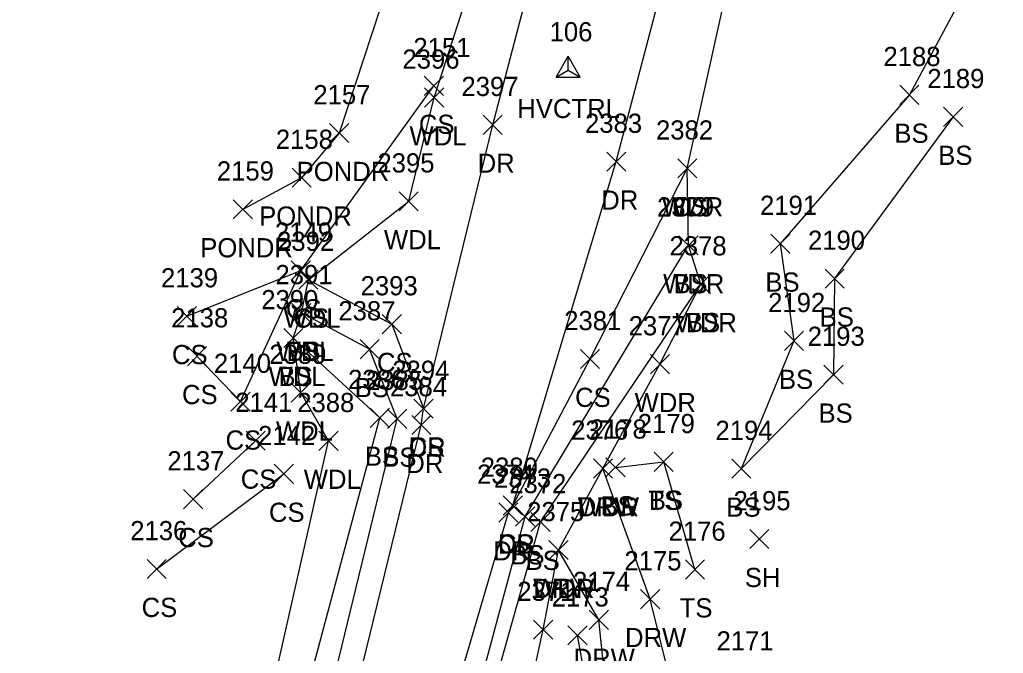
# Model space of a CAD drawing. Extents: x 1761340 to 1763889, y 696770 to 706023.
# Drawn here: x 1761653.6 to 1761756.2, y 700983.6 to 701049.7 of the extents above; entities that cross this region are included whole.
import ezdxf

# ---------------------------------------------------------------- set-up
doc = ezdxf.new("R2010")
doc.units = 0
for name, color, linetype in [('C_A', 7, 'Continuous'), ('C_I', 7, 'Continuous'), ('CPSM', 7, 'Continuous'), ('L_A', 7, 'Continuous'), ('L_I', 7, 'Continuous'), ('L_TIC', 7, 'Continuous'), ('LAWA', 7, 'Continuous'), ('LAWE', 7, 'Continuous'), ('LELB', 7, 'Continuous'), ('R_A', 7, 'Continuous'), ('R_I', 7, 'Continuous'), ('R_TIC', 7, 'Continuous'), ('RDP', 7, 'Continuous'), ('RDW', 7, 'Continuous')]:
    doc.layers.add(name, color=color, linetype=linetype)

msp = doc.modelspace()

# ---------------------------------------------------------------- linework, layer by layer
at = {"layer": 'CPSM'}
for p, q in [((1761709.57, 701043.69), (1761710.82, 701045.86)), ((1761712.07, 701043.69), (1761710.82, 701045.86)), ((1761710.82, 701044.42), (1761710.82, 701045.86)), ((1761709.57, 701043.69), (1761710.82, 701044.42)), ((1761710.82, 701044.42), (1761710.82, 701044.42)), ((1761710.82, 701044.42), (1761712.07, 701043.69)), ((1761709.57, 701043.69), (1761712.07, 701043.69))]:
    msp.add_line(p, q, dxfattribs=at)
at = {"layer": 'L_TIC'}
for points in [[(1761695.82, 701041.77), (1761697.82, 701043.77)], [(1761697.82, 701041.77), (1761695.82, 701043.77)], [(1761695.86, 701040.57), (1761697.86, 701042.57)], [(1761697.86, 701040.57), (1761695.86, 701042.57)], [(1761745.39, 701040.84), (1761747.39, 701042.84)], [(1761747.39, 701040.84), (1761745.39, 701042.84)], [(1761749.96, 701038.54), (1761751.96, 701040.54)], [(1761751.96, 701038.54), (1761749.96, 701040.54)], [(1761685.95, 701036.86), (1761687.95, 701038.86)], [(1761687.95, 701036.86), (1761685.95, 701038.86)], [(1761722.24, 701033.18), (1761724.24, 701035.18)], [(1761724.24, 701033.18), (1761722.24, 701035.18)], [(1761722.24, 701033.18), (1761724.24, 701035.18)], [(1761724.24, 701033.18), (1761722.24, 701035.18)], [(1761682.04, 701032.21), (1761684.04, 701034.21)], [(1761684.04, 701032.21), (1761682.04, 701034.21)], [(1761693.2, 701029.75), (1761695.2, 701031.75)], [(1761695.2, 701029.75), (1761693.2, 701031.75)], [(1761675.9, 701028.91), (1761677.9, 701030.91)], [(1761677.9, 701028.91), (1761675.9, 701030.91)], [(1761722.36, 701025.16), (1761724.36, 701027.16)], [(1761724.36, 701025.16), (1761722.36, 701027.16)], [(1761722.36, 701025.16), (1761724.36, 701027.16)], [(1761724.36, 701025.16), (1761722.36, 701027.16)], [(1761731.94, 701025.33), (1761733.94, 701027.33)], [(1761733.94, 701025.33), (1761731.94, 701027.33)], [(1761681.96, 701022.54), (1761683.96, 701024.54)], [(1761683.96, 701022.54), (1761681.96, 701024.54)], [(1761681.96, 701022.54), (1761683.96, 701024.54)], [(1761683.96, 701022.54), (1761681.96, 701024.54)], [(1761682.74, 701021.58), (1761684.74, 701023.58)], [(1761684.74, 701021.58), (1761682.74, 701023.58)], [(1761682.74, 701021.58), (1761684.74, 701023.58)], [(1761684.74, 701021.58), (1761682.74, 701023.58)], [(1761723.65, 701021.11), (1761725.65, 701023.11)], [(1761725.65, 701021.11), (1761723.65, 701023.11)], [(1761723.65, 701021.11), (1761725.65, 701023.11)], [(1761725.65, 701021.11), (1761723.65, 701023.11)], [(1761737.6, 701021.69), (1761739.6, 701023.69)], [(1761739.6, 701021.69), (1761737.6, 701023.69)], [(1761670.08, 701017.78), (1761672.08, 701019.78)], [(1761672.08, 701017.78), (1761670.08, 701019.78)], [(1761682.01, 701018.11), (1761684.01, 701020.11)], [(1761684.01, 701018.11), (1761682.01, 701020.11)], [(1761682.01, 701018.11), (1761684.01, 701020.11)], [(1761684.01, 701018.11), (1761682.01, 701020.11)], [(1761691.44, 701016.95), (1761693.44, 701018.95)], [(1761693.44, 701016.95), (1761691.44, 701018.95)], [(1761681.17, 701015.5), (1761683.17, 701017.5)], [(1761683.17, 701015.5), (1761681.17, 701017.5)], [(1761681.17, 701015.5), (1761683.17, 701017.5)], [(1761683.17, 701015.5), (1761681.17, 701017.5)], [(1761733.36, 701015.2), (1761735.36, 701017.2)], [(1761735.36, 701015.2), (1761733.36, 701017.2)], [(1761689.13, 701014.34), (1761691.13, 701016.34)], [(1761691.13, 701014.34), (1761689.13, 701016.34)], [(1761671.13, 701013.61), (1761673.13, 701015.61)], [(1761673.13, 701013.61), (1761671.13, 701015.61)], [(1761712.1, 701013.32), (1761714.1, 701015.32)], [(1761714.1, 701013.32), (1761712.1, 701015.32)], [(1761719.39, 701012.78), (1761721.39, 701014.78)], [(1761721.39, 701012.78), (1761719.39, 701014.78)], [(1761737.48, 701011.68), (1761739.48, 701013.68)], [(1761739.48, 701011.68), (1761737.48, 701013.68)], [(1761681.94, 701009.81), (1761683.94, 701011.81)], [(1761683.94, 701009.81), (1761681.94, 701011.81)], [(1761675.67, 701008.87), (1761677.67, 701010.87)], [(1761677.67, 701008.87), (1761675.67, 701010.87)], [(1761694.75, 701008.14), (1761696.75, 701010.14)], [(1761696.75, 701008.14), (1761694.75, 701010.14)], [(1761690.19, 701007.19), (1761692.19, 701009.19)], [(1761692.19, 701007.19), (1761690.19, 701009.19)], [(1761692, 701007.08), (1761694, 701009.08)], [(1761694, 701007.08), (1761692, 701009.08)], [(1761677.24, 701004.8), (1761679.24, 701006.8)], [(1761679.24, 701004.8), (1761677.24, 701006.8)], [(1761684.84, 701004.78), (1761686.84, 701006.78)], [(1761686.84, 701004.78), (1761684.84, 701006.78)], [(1761719.78, 701002.59), (1761721.78, 701004.59)], [(1761721.78, 701002.59), (1761719.78, 701004.59)], [(1761719.78, 701002.59), (1761721.78, 701004.59)], [(1761721.78, 701002.59), (1761719.78, 701004.59)], [(1761713.45, 701001.91), (1761715.45, 701003.91)], [(1761715.45, 701001.91), (1761713.45, 701003.91)], [(1761714.76, 701002.02), (1761716.76, 701004.02)], [(1761716.76, 701002.02), (1761714.76, 701004.02)], [(1761727.87, 701001.88), (1761729.87, 701003.88)], [(1761729.87, 701001.88), (1761727.87, 701003.88)], [(1761727.87, 701001.88), (1761729.87, 701003.88)], [(1761729.87, 701001.88), (1761727.87, 701003.88)], [(1761680.19, 701001.34), (1761682.19, 701003.34)], [(1761682.19, 701001.34), (1761680.19, 701003.34)], [(1761670.73, 700998.71), (1761672.73, 701000.71)], [(1761672.73, 700998.71), (1761670.73, 701000.71)], [(1761704.06, 700998.04), (1761706.06, 701000.04)], [(1761706.06, 700998.04), (1761704.06, 701000.04)], [(1761705.35, 700996.91), (1761707.35, 700998.91)], [(1761707.35, 700996.91), (1761705.35, 700998.91)], [(1761706.94, 700996.33), (1761708.94, 700998.33)], [(1761708.94, 700996.33), (1761706.94, 700998.33)], [(1761729.75, 700994.55), (1761731.75, 700996.55)], [(1761731.75, 700994.55), (1761729.75, 700996.55)], [(1761708.81, 700993.41), (1761710.81, 700995.41)], [(1761710.81, 700993.41), (1761708.81, 700995.41)], [(1761666.92, 700991.43), (1761668.92, 700993.43)], [(1761668.92, 700991.43), (1761666.92, 700993.43)], [(1761723.04, 700991.38), (1761725.04, 700993.38)], [(1761725.04, 700991.38), (1761723.04, 700993.38)], [(1761707.21, 700985.11), (1761709.21, 700987.11)], [(1761709.21, 700985.11), (1761707.21, 700987.11)], [(1761710.79, 700984.52), (1761712.79, 700986.52)], [(1761712.79, 700984.52), (1761710.79, 700986.52)]]:
    msp.add_lwpolyline(points, dxfattribs=at)
at = {"layer": 'LAWA'}
for points in [[(1761667.45, 700938.83), (1761676.85, 700965.95), (1761685.84, 701005.78), (1761682.94, 701010.81), (1761682.17, 701016.5), (1761683.01, 701019.11), (1761683.74, 701022.58), (1761694.2, 701030.75), (1761696.86, 701041.57), (1761703.63, 701062.52), (1761706.63, 701075.37), (1761702.24, 701098.48), (1761699.3, 701099.16), (1761706.74, 701121.1), (1761714.05, 701139.55)], [(1761683.19, 700893.77), (1761693.76, 700930.8), (1761702.56, 700960.09), (1761708.21, 700986.11), (1761709.81, 700994.41), (1761714.45, 701002.91), (1761720.39, 701013.78), (1761724.65, 701022.11), (1761723.36, 701026.16), (1761723.24, 701034.18), (1761732.59, 701076.41), (1761747, 701128.03)]]:
    msp.add_lwpolyline(points, dxfattribs=at)
at = {"layer": 'LAWE'}
msp.add_lwpolyline([(1761695.98, 701076.99), (1761695.44, 701063.67), (1761686.95, 701037.86), (1761683.04, 701033.21), (1761676.9, 701029.91)], dxfattribs=at)
at = {"layer": 'LELB'}
for points in [[(1761765.71, 701062.95), (1761753.76, 701055.58), (1761746.39, 701041.84), (1761732.94, 701026.33), (1761734.36, 701016.2), (1761728.87, 701002.88)], [(1761672.13, 701014.61), (1761676.67, 701009.87), (1761682.96, 701023.54), (1761696.82, 701042.77)], [(1761750.96, 701039.54), (1761738.6, 701022.69), (1761738.48, 701012.68), (1761728.87, 701002.88)], [(1761705.06, 700999.04), (1761713.1, 701014.32), (1761723.24, 701034.18)], [(1761681.3, 700585.52), (1761671.93, 700613.51), (1761667.59, 700648.27), (1761662.96, 700684.4), (1761660.97, 700720.86), (1761660.49, 700762.08), (1761662.81, 700791.59), (1761666.16, 700822.15), (1761669.09, 700835.75), (1761669.55, 700847.22), (1761671.38, 700859.7), (1761679.65, 700896.38), (1761688.23, 700933.04), (1761696.4, 700960.96), (1761706.35, 700997.91), (1761723.36, 701026.16)], [(1761671.08, 701018.78), (1761682.96, 701023.54)], [(1761684.45, 700586.47), (1761674.15, 700613.84), (1761669.56, 700648.24), (1761665.94, 700684.58), (1761663.69, 700720.73), (1761662.67, 700762.27), (1761665.11, 700791.25), (1761666.95, 700822.18), (1761669.97, 700835.61), (1761670.38, 700847.09), (1761671.95, 700859.51), (1761680.67, 700895.81), (1761689.74, 700932.61), (1761697.72, 700961.08), (1761707.94, 700997.33), (1761724.65, 701022.11)], [(1761683.74, 701022.58), (1761692.44, 701017.95), (1761695.75, 701009.14)], [(1761650.67, 700568.58), (1761653.72, 700589.35), (1761656.23, 700611.85), (1761650.78, 700645.88), (1761646.69, 700682.27), (1761643.97, 700721.14), (1761646.18, 700763.15), (1761649, 700791.97), (1761651.08, 700826.68), (1761655.56, 700862.86), (1761665.44, 700900.35), (1761673.53, 700937.72), (1761682.38, 700964.35), (1761693, 701008.08), (1761690.13, 701015.34), (1761683.01, 701019.11)], [(1761647.36, 700568.69), (1761651.51, 700589.64), (1761652.18, 700611.17), (1761648.15, 700645.92), (1761644.28, 700683.03), (1761641.56, 700721.37), (1761643.75, 700763.66), (1761644.59, 700792.45), (1761648.47, 700827.4), (1761652.74, 700863.51), (1761659.58, 700901.67), (1761670.1, 700938.53), (1761679.51, 700964.49), (1761691.19, 701008.19), (1761682.17, 701016.5)], [(1761671.73, 700999.71), (1761678.24, 701005.8)], [(1761715.76, 701003.02), (1761720.78, 701003.59)], [(1761724.04, 700992.38), (1761720.78, 701003.59)], [(1761667.92, 700992.43), (1761681.19, 701002.34)], [(1761715.79, 700954.75), (1761714.13, 700972.59), (1761711.79, 700985.52)]]:
    msp.add_lwpolyline(points, dxfattribs=at)
at = {"layer": 'R_TIC'}
for points in [[(1761701.96, 701037.72), (1761703.96, 701039.72)], [(1761703.96, 701037.72), (1761701.96, 701039.72)], [(1761714.84, 701033.88), (1761716.84, 701035.88)], [(1761716.84, 701033.88), (1761714.84, 701035.88)], [(1761694.75, 701008.14), (1761696.75, 701010.14)], [(1761696.75, 701008.14), (1761694.75, 701010.14)], [(1761694.51, 701006.43), (1761696.51, 701008.43)], [(1761696.51, 701006.43), (1761694.51, 701008.43)], [(1761713.45, 701001.91), (1761715.45, 701003.91)], [(1761715.45, 701001.91), (1761713.45, 701003.91)], [(1761703.59, 700997.32), (1761705.59, 700999.32)], [(1761705.59, 700997.32), (1761703.59, 700999.32)], [(1761704.06, 700998.04), (1761706.06, 701000.04)], [(1761706.06, 700998.04), (1761704.06, 701000.04)], [(1761708.81, 700993.41), (1761710.81, 700995.41)], [(1761710.81, 700993.41), (1761708.81, 700995.41)], [(1761718.38, 700988.29), (1761720.38, 700990.29)], [(1761720.38, 700988.29), (1761718.38, 700990.29)], [(1761713.02, 700986.14), (1761715.02, 700988.14)], [(1761715.02, 700986.14), (1761713.02, 700988.14)]]:
    msp.add_lwpolyline(points, dxfattribs=at)
at = {"layer": 'RDP'}
for points in [[(1761671.26, 700538.43), (1761661.64, 700574.62), (1761657.61, 700611.79), (1761653.18, 700645.74), (1761649.93, 700682.03), (1761646.9, 700721.23), (1761649.1, 700763.06), (1761651.35, 700791.61), (1761653.66, 700826.22), (1761659.48, 700861.88), (1761668.31, 700899.37), (1761676.77, 700936.6), (1761684.87, 700963.93), (1761695.51, 701007.43), (1761695.75, 701009.14), (1761702.96, 701038.72), (1761714.69, 701083.39), (1761730.25, 701133.73)], [(1761685.9, 700541.84), (1761678.4, 700578.09), (1761669.59, 700613.17), (1761665.81, 700647.63), (1761660.31, 700684.32), (1761659.55, 700721.03), (1761658.73, 700762.09), (1761660.8, 700791.69), (1761663.62, 700822.45), (1761666.15, 700836.34), (1761667.52, 700847.08), (1761668.95, 700859.68), (1761676.88, 700896.8), (1761686.16, 700933.2), (1761693.93, 700961.97), (1761704.59, 700998.32), (1761705.06, 700999.04), (1761715.84, 701034.88), (1761727.08, 701077.74), (1761742.29, 701129.68)]]:
    msp.add_lwpolyline(points, dxfattribs=at)
at = {"layer": 'RDW'}
for points in [[(1761719.38, 700989.29), (1761714.45, 701002.91)], [(1761714.02, 700987.14), (1761709.81, 700994.41)], [(1761723.9, 700959.41), (1761722.69, 700975.85), (1761719.38, 700989.29)], [(1761716.97, 700954.98), (1761715.48, 700973.05), (1761714.02, 700987.14)]]:
    msp.add_lwpolyline(points, dxfattribs=at)

# ---------------------------------------------------------------- texts
at = {"layer": 'C_A'}
msp.add_text('HVCTRL', height=2, dxfattribs=at).set_placement((1761705.52, 701039.42))
at = {"layer": 'C_I'}
msp.add_text('106', height=2, dxfattribs=at).set_placement((1761708.89, 701047.42))
at = {"layer": 'L_A'}
for s, p in [('CS', (1761695.26, 701037.77)), ('WDL', (1761694.28, 701036.57)), ('BS', (1761744.83, 701036.84)), ('BS', (1761749.4, 701034.54)), ('PONDR', (1761682.52, 701032.86)), ('WDR', (1761720.6, 701029.18)), ('CS', (1761721.68, 701029.18)), ('PONDR', (1761678.61, 701028.21)), ('WDL', (1761691.62, 701025.75)), ('PONDR', (1761672.47, 701024.91)), ('WDR', (1761720.72, 701021.16)), ('BS', (1761721.8, 701021.16)), ('BS', (1761731.38, 701021.33)), ('CS', (1761681.4, 701018.54)), ('CS', (1761681.4, 701018.54)), ('WDL', (1761681.16, 701017.58)), ('CS', (1761682.18, 701017.58)), ('WDR', (1761722.02, 701017.11)), ('BS', (1761723.1, 701017.11)), ('BS', (1761737.04, 701017.69)), ('CS', (1761669.52, 701013.78)), ('WDL', (1761680.42, 701014.11)), ('BS', (1761681.45, 701014.11)), ('CS', (1761690.89, 701012.95)), ('WDL', (1761679.59, 701011.5)), ('BS', (1761680.62, 701011.5)), ('BS', (1761732.8, 701011.2)), ('CS', (1761670.57, 701009.61)), ('BS', (1761688.57, 701010.34)), ('CS', (1761711.54, 701009.32)), ('WDR', (1761717.75, 701008.78)), ('BS', (1761736.92, 701007.68)), ('WDL', (1761680.36, 701005.81)), ('CS', (1761675.11, 701004.87)), ('CS', (1761694.2, 701004.14)), ('BS', (1761689.63, 701003.19)), ('BS', (1761691.44, 701003.08)), ('CS', (1761676.69, 701000.8)), ('WDL', (1761683.26, 701000.78)), ('TS', (1761719.19, 700998.59)), ('BS', (1761719.23, 700998.59)), ('CS', (1761679.63, 700997.34)), ('WDR', (1761711.82, 700997.91)), ('BS', (1761714.2, 700998.02)), ('BS', (1761727.31, 700997.88)), ('BS', (1761727.31, 700997.88)), ('CS', (1761670.17, 700994.71)), ('CS', (1761703.5, 700994.04)), ('BS', (1761704.79, 700992.91)), ('BS', (1761706.38, 700992.33)), ('SH', (1761729.24, 700990.55)), ('WDR', (1761707.17, 700989.41)), ('CS', (1761666.36, 700987.43)), ('TS', (1761722.45, 700987.38))]:
    msp.add_text(s, height=2, dxfattribs=at).set_placement(p)
at = {"layer": 'L_I'}
for s, p in [('2151', (1761694.69, 701045.77)), ('2396', (1761693.55, 701044.57)), ('2188', (1761743.69, 701044.84)), ('2189', (1761748.26, 701042.54)), ('2157', (1761684.26, 701040.86)), ('2158', (1761680.35, 701036.21)), ('2382', (1761719.98, 701037.18)), ('2382', (1761719.98, 701037.18)), ('2395', (1761690.94, 701033.75)), ('2159', (1761674.2, 701032.91)), ('2379', (1761720.09, 701029.16)), ('2379', (1761720.09, 701029.16)), ('2191', (1761730.82, 701029.33)), ('2149', (1761680.26, 701026.54)), ('2149', (1761680.26, 701026.54)), ('2392', (1761680.48, 701025.58)), ('2392', (1761680.48, 701025.58)), ('2378', (1761721.39, 701025.11)), ('2378', (1761721.39, 701025.11)), ('2190', (1761735.82, 701025.69)), ('2391', (1761680.31, 701022.11)), ('2391', (1761680.31, 701022.11)), ('2139', (1761668.38, 701021.78)), ('2393', (1761689.19, 701020.95)), ('2390', (1761678.83, 701019.5)), ('2390', (1761678.83, 701019.5)), ('2192', (1761731.67, 701019.2)), ('2387', (1761686.87, 701018.34)), ('2138', (1761669.44, 701017.61)), ('2381', (1761710.41, 701017.32)), ('2377', (1761717.13, 701016.78)), ('2193', (1761735.79, 701015.68)), ('2389', (1761679.67, 701013.81)), ('2140', (1761673.89, 701012.87)), ('2394', (1761692.49, 701012.14)), ('2386', (1761687.88, 701011.19)), ('2385', (1761689.74, 701011.08)), ('2141', (1761676.12, 701008.8)), ('2388', (1761682.58, 701008.78)), ('2179', (1761718.08, 701006.59)), ('2179', (1761718.08, 701006.59)), ('2376', (1761711.14, 701005.91)), ('2178', (1761713.07, 701006.02)), ('2194', (1761726.18, 701005.88)), ('2194', (1761726.18, 701005.88)), ('2142', (1761678.5, 701005.34)), ('2137', (1761669.04, 701002.71)), ('2380', (1761701.71, 701002.04)), ('2373', (1761703.09, 701000.91)), ('2372', (1761704.68, 701000.33)), ('2195', (1761728.06, 700998.55)), ('2375', (1761706.55, 700997.41)), ('2136', (1761665.17, 700995.43)), ('2176', (1761721.29, 700995.38)), ('2371', (1761705.52, 700989.11)), ('2173', (1761709.1, 700988.52)), ('2171', (1761726.29, 700983.94))]:
    msp.add_text(s, height=2, dxfattribs=at).set_placement(p)
at = {"layer": 'R_A'}
for s, p in [('DR', (1761701.39, 701033.72)), ('DR', (1761714.27, 701029.88)), ('DR', (1761694.19, 701004.14)), ('DR', (1761693.95, 701002.43)), ('DRW', (1761711.82, 700997.91)), ('DR', (1761703.02, 700993.32)), ('DR', (1761703.49, 700994.04)), ('DRW', (1761707.18, 700989.41)), ('DRW', (1761716.75, 700984.29)), ('DRW', (1761711.39, 700982.14))]:
    msp.add_text(s, height=2, dxfattribs=at).set_placement(p)
at = {"layer": 'R_I'}
for s, p in [('2397', (1761699.7, 701041.72)), ('2383', (1761712.58, 701037.88)), ('2394', (1761692.49, 701012.14)), ('2384', (1761692.25, 701010.43)), ('2376', (1761711.14, 701005.91)), ('2380', (1761701.71, 701002.04)), ('2374', (1761701.33, 701001.32)), ('2375', (1761706.55, 700997.41)), ('2175', (1761716.69, 700992.29)), ('2174', (1761711.33, 700990.14))]:
    msp.add_text(s, height=2, dxfattribs=at).set_placement(p)

doc.saveas('drawing.dxf')
